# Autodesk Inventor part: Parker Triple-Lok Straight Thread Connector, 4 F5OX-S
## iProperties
Shininess: 20.0
Length Units: 11272
Angle Units: 11279
Time Units: 11290
Mass Units: 11286
Length Display Precision: 3
Angle Display Precision: 2
Created: 2001-09
Part Number: Parker Triple-Lok Straight Thread Connector, 4 F5OX-S
Material: Stainless Steel, Austenitic
Description: Parker Triple-Lok Straight Thread Connector, 4 F5OX-S
Document SubType Name: Modeling
Designer: jhagarty
Density: 0.0
Volumn: 0.0
Area: 0.0
PropertySet Name: Model Information
Control State: 0
Master: False
Checked Out: False
Last Check In By: Charles Bliss
Last Check In Date: 2003-09-27
Author: jhagarty
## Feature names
1. Extrusion1
2. Revolution3
3. Mirror2
4. Revolution1
5. Extrusion2
6. Extrusion3
7. Hole2
8. Hole3
9. Chamfer1
10. Chamfer2
11. Revolution5
